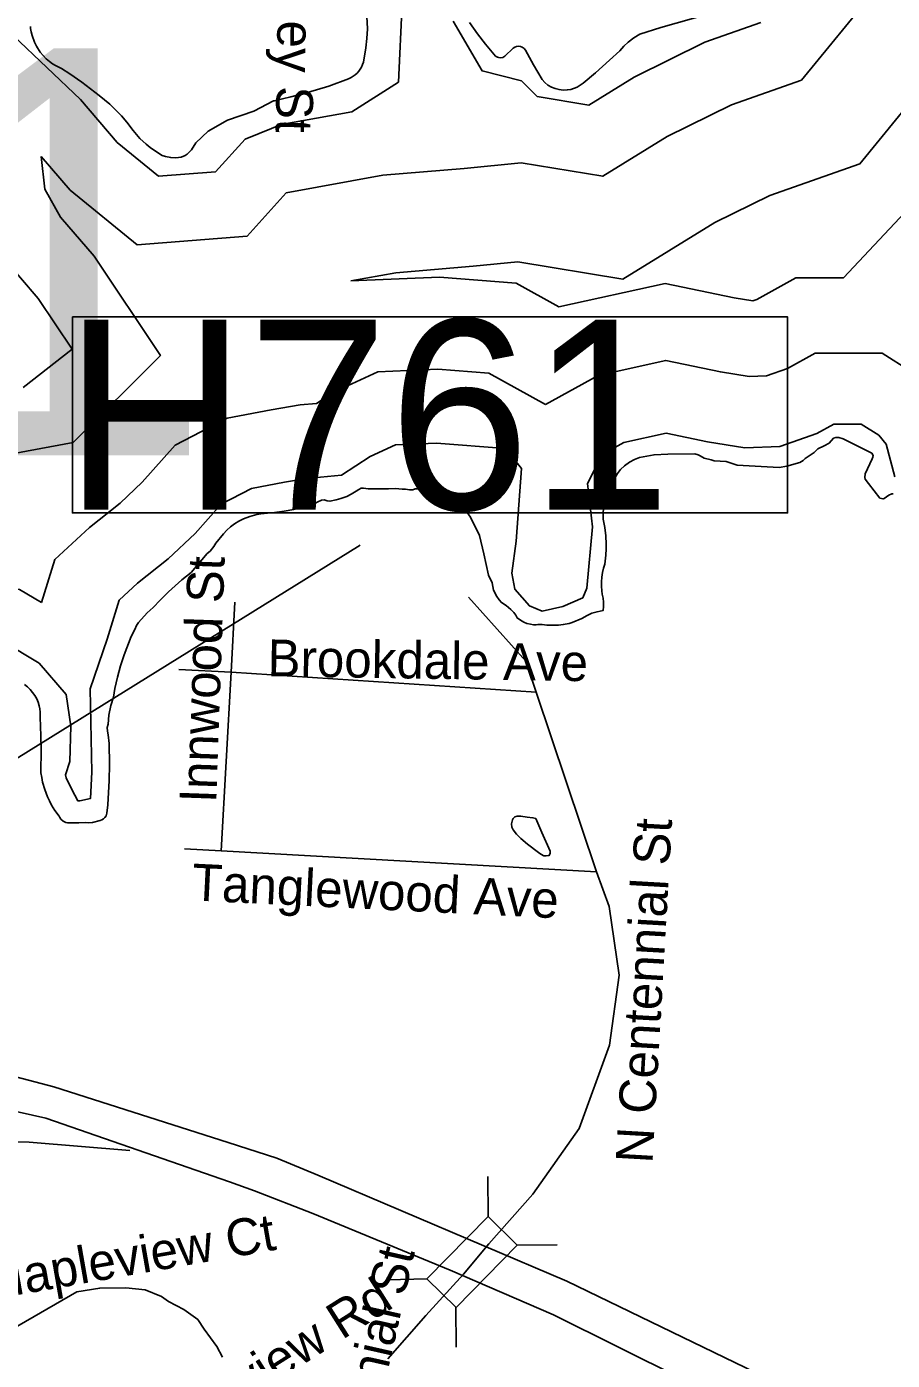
# Model space of a CAD drawing. Extents: x 1662474 to 1856135, y 779280 to 917889.
# Drawn here: x 1702297 to 1704529, y 822946 to 826386 of the extents above; entities that cross this region are included whole.
import ezdxf

# ---------------------------------------------------------------- set-up
doc = ezdxf.new("R2010")
doc.units = 0
for name, color, linetype in [('Exist Hydrographic Lake Shore', 7, 'Continuous'), ('Exist Hydrographic Misc Water Feature', 7, 'Continuous'), ('Exist Road Non-System Structure Non-Sys NCDOT Attributed CELL', 7, 'Continuous'), ('Exist Road Non-System Structure Non-Sys NCDOT Number Label', 7, 'Continuous'), ('Exist Road Non-System Structure Non-Sys Other Number Label', 7, 'Continuous'), ('Exist Road Non-System Type 51', 7, 'Continuous'), ('Exist Road Non-System Type 51 Label', 7, 'Continuous'), ('Exist Road Primary US Divided Attributed', 7, 'Continuous'), ('Old_Level_44', 7, 'Continuous')]:
    doc.layers.add(name, color=color, linetype=linetype)

msp = doc.modelspace()

# ---------------------------------------------------------------- linework, layer by layer
at = {"layer": 'Exist Hydrographic Lake Shore'}
for points in [[(1703439.2, 826397.1), (1703459.2, 826368.2), (1703480.2, 826341.4), (1703506.2, 826310.5), (1703511, 826307.6), (1703514.4, 826306.6), (1703519.6, 826306), (1703524.6, 826307.1), (1703530.1, 826310.5), (1703551.6, 826330.7), (1703555.9, 826333.6), (1703560.5, 826335.4), (1703565.8, 826335.9), (1703570, 826335.4), (1703575, 826333.9), (1703579.8, 826330.4), (1703583.4, 826326), (1703603.9, 826287.6), (1703625.9, 826249.9), (1703633, 826242.2), (1703641.1, 826235.7), (1703650.2, 826230.4), (1703659.8, 826226.5), (1703670, 826224.1), (1703680.2, 826222.8), (1703690.8, 826223.1), (1703700.1, 826224.7), (1703716.5, 826230.7), (1703732.2, 826240.9), (1703763.4, 826267.4), (1703799.9, 826299.8), (1703826.6, 826324.4), (1703836.6, 826335.7), (1703848, 826346.2), (1703862.4, 826357.5), (1703878.1, 826367.2), (1703932.2, 826384.2), (1704050.9, 826417.8)], [(1702306.8, 826386.9), (1702307.2, 826381.9), (1702308.9, 826372.7), (1702311, 826363.8), (1702317, 826346.4), (1702322.2, 826336.2), (1702332.2, 826321), (1702339.6, 826312.1), (1702347.8, 826303.7), (1702356.4, 826296.3), (1702363.8, 826290.8), (1702371.6, 826286.1), (1702387.1, 826278.4), (1702408.6, 826264.6), (1702439.2, 826243.1), (1702483.9, 826208.9), (1702511.2, 826186.4), (1702527, 826171.4), (1702541.4, 826156.2), (1702555, 826140.4)], [(1702555, 826140.4), (1702571.9, 826118.1), (1702580.2, 826107.9), (1702589.1, 826098.2), (1702605.5, 826082.9), (1702615.6, 826074.6), (1702626.5, 826066.7), (1702646.9, 826053.8), (1702655.4, 826051.4), (1702668.8, 826048.8), (1702682.1, 826048.3), (1702695.8, 826049.3), (1702706, 826054.3), (1702710.8, 826057.5), (1702715.6, 826061.9), (1702722, 826069), (1702733.5, 826086.6), (1702764.8, 826116.8), (1702815.1, 826144.9), (1702882.6, 826168.5), (1702933.2, 826195), (1702935.4, 826195), (1702978.6, 826205), (1703021.5, 826216.5), (1703076.2, 826233.3), (1703126.8, 826251.4), (1703133.8, 826254.9), (1703144, 826261.9), (1703149, 826266.7), (1703153.8, 826271.6), (1703160.2, 826282.1), (1703163.1, 826288.4), (1703165.2, 826294.8), (1703171.6, 826332.2), (1703174.2, 826356.2), (1703175.5, 826380.6), (1703174, 826412.6)], [(1704531.4, 825181.6), (1704527.5, 825180.9), (1704520.4, 825177.9), (1704507.8, 825168.8), (1704505.4, 825168), (1704497.2, 825170.4), (1704467.4, 825207.6), (1704459.2, 825219.2), (1704458.1, 825223.6), (1704459.2, 825232.8), (1704477.1, 825271.4), (1704478.6, 825275.9), (1704479.4, 825280.3), (1704475.8, 825286.4), (1704402.5, 825323.4), (1704391, 825326.8), (1704383.6, 825326.8), (1704377.4, 825324.4), (1704366.2, 825311.8), (1704353.1, 825304.8), (1704336.6, 825296.9), (1704327.2, 825288.2), (1704304.4, 825272.4), (1704299.1, 825267.4), (1704291, 825262.2), (1704257.4, 825252.8), (1704237.1, 825249.4), (1704129, 825255.4), (1704101, 825264.8), (1704069.8, 825265.9), (1704061.6, 825269.1), (1704043.5, 825273), (1704034, 825278.8), (1704028.8, 825281.4), (1704019.6, 825284.5), (1703950, 825283.5), (1703914.6, 825282.2), (1703877.4, 825274.6), (1703864, 825269.6), (1703851.4, 825263), (1703838.2, 825253.6), (1703828.2, 825243.6), (1703820.6, 825233.9), (1703814.4, 825223.1), (1703808.9, 825210), (1703804.9, 825196.1), (1703799.1, 825186.6), (1703792.6, 825173.5), (1703788.4, 825161.4), (1703785.2, 825147), (1703783.6, 825134.4), (1703783.4, 825123.9), (1703783.9, 825115.5), (1703785, 825107.1), (1703787.9, 825094.5), (1703790.2, 825072.7), (1703791.2, 825051.2), (1703791.2, 825039.1), (1703790.2, 825022.6), (1703787.4, 825000), (1703784.4, 824989.5), (1703782.1, 824977.9), (1703780.2, 824966.4), (1703779.5, 824954.6), (1703779.5, 824942.6), (1703780, 824930.8), (1703781.2, 824922.1), (1703783.1, 824912.1), (1703784.4, 824902.1), (1703784.4, 824890.3), (1703783.6, 824880.3), (1703767.9, 824877.2), (1703754.5, 824873), (1703742.1, 824867.2), (1703728.2, 824859.3), (1703703.6, 824849.1), (1703695.5, 824846.8), (1703680.8, 824844.1), (1703668.6, 824842.6), (1703653.5, 824842), (1703638.2, 824842.8), (1703626.4, 824844.4), (1703615.9, 824844.4), (1703610.6, 824843.1), (1703603.9, 824843.6), (1703596, 824844.6)], [(1703596, 824844.6), (1703587, 824847), (1703578.6, 824850.4), (1703570.5, 824854.9), (1703562.1, 824861.2), (1703558.5, 824868.2), (1703553.5, 824874.8), (1703548.8, 824879), (1703545.4, 824883.2), (1703533.8, 824892.7), (1703521.1, 824900.8), (1703515.1, 824907.9), (1703509.6, 824916.6), (1703501.2, 824933.1), (1703497.5, 824951.2), (1703487.6, 824971.4), (1703476, 825026.8), (1703464.8, 825073.5), (1703441.4, 825120.8), (1703419.9, 825150.7), (1703402.8, 825165.9), (1703369.5, 825186.1), (1703333, 825191.9), (1703325.9, 825191.6), (1703317.8, 825194.5), (1703298.9, 825193.7), (1703293.1, 825191.9), (1703284.4, 825191.9), (1703274, 825192.9), (1703265.5, 825193.2), (1703247.8, 825194.8), (1703230.4, 825194), (1703177.9, 825194.2), (1703165.2, 825195.8), (1703159.5, 825195.6), (1703153.2, 825192.7), (1703146.6, 825187.7), (1703134, 825180.3), (1703122.5, 825174.3), (1703106.8, 825168.8), (1703095, 825165.6), (1703078.9, 825161.9), (1703071.6, 825162.8), (1703064.2, 825165.4), (1703057.1, 825164.8), (1703046.1, 825160.1), (1703035.4, 825153), (1703010.1, 825146.8), (1702985.8, 825141.2), (1702960.9, 825136.8), (1702936.1, 825133.1), (1702900.8, 825129.4), (1702890.2, 825127.8), (1702872.6, 825123.1), (1702855.9, 825116.6), (1702844, 825110.8), (1702833.2, 825103.7), (1702822.8, 825095.8), (1702813.4, 825087.1), (1702804.4, 825077.7), (1702785.2, 825054.1), (1702779.5, 825045.2), (1702770.5, 825033.6), (1702762.9, 825027.1), (1702721.5, 824978.5), (1702697.6, 824959.1), (1702663.2, 824928.1), (1702641.4, 824906.6), (1702623.2, 824887.7), (1702607.8, 824874.1), (1702585.5, 824849.6), (1702580, 824841.2), (1702575.8, 824831.2), (1702566.9, 824812.9), (1702548.8, 824765.9), (1702539.2, 824737.3), (1702531.1, 824708.4), (1702524.6, 824679.3), (1702520.9, 824656.4), (1702514.4, 824635.4), (1702509.4, 824609.8), (1702507.2, 824587.4), (1702505.1, 824578.8), (1702505.8, 824569.3), (1702507.2, 824559.3), (1702509.6, 824537.1), (1702510.8, 824483.2), (1702509.9, 824441.5), (1702506, 824379), (1702503.6, 824357.2), (1702501.8, 824350.7), (1702498.9, 824346.5), (1702495.5, 824342.8), (1702491.2, 824339.9), (1702486.5, 824338.1), (1702466.6, 824333.6), (1702457.6, 824332.8), (1702448.5, 824333.6), (1702431.4, 824332.6), (1702406.5, 824332.3)], [(1702385.2, 824342.3), (1702382.6, 824346.2), (1702380.8, 824349.6), (1702370, 824364.6), (1702361.6, 824378.2), (1702355.9, 824388.8), (1702350.9, 824399.8), (1702343.8, 824418.4), (1702338.2, 824437.6), (1702335.9, 824449.4), (1702333.8, 824461.2), (1702334.4, 824521.3), (1702333.8, 824557), (1702331.8, 824605.2), (1702332, 824618.1), (1702331.1, 824626.2), (1702329.6, 824634.1), (1702326.8, 824643.6), (1702323, 824652.5), (1702318, 824661.2), (1702312.5, 824669.1), (1702306.2, 824676.4), (1702299.1, 824683.2), (1702291.2, 824689.2)], [(1702406.5, 824332.3), (1702402.6, 824332.6), (1702397.9, 824333.6), (1702391, 824337.1), (1702385.2, 824342.3)]]:
    msp.add_lwpolyline(points, dxfattribs=at)
at = {"layer": 'Exist Hydrographic Misc Water Feature'}
msp.add_lwpolyline([(1703625.6, 824307.2), (1703609.6, 824343.6), (1703602.4, 824345.4), (1703587.7, 824347.4), (1703570.9, 824349.4), (1703561.5, 824349.6), (1703555.8, 824348), (1703551.6, 824344), (1703549.7, 824339.9), (1703547.6, 824330.1), (1703548.1, 824321.1), (1703551.5, 824314.4), (1703560, 824303.6), (1703571.1, 824291.8), (1703588.8, 824277.5), (1703616.7, 824255.7), (1703622.5, 824251.4), (1703630.4, 824247.2), (1703636.4, 824247), (1703644.5, 824248.5), (1703646.8, 824254.2), (1703646.7, 824259.2), (1703625.6, 824307.2)], dxfattribs=at)
msp.add_lwpolyline([(1703625.6, 824307.2), (1703609.6, 824343.6), (1703602.4, 824345.4), (1703587.7, 824347.4), (1703570.9, 824349.4), (1703561.5, 824349.6), (1703555.8, 824348), (1703551.6, 824344), (1703549.7, 824339.9), (1703547.6, 824330.1), (1703548.1, 824321.1), (1703551.5, 824314.4), (1703560, 824303.6), (1703571.1, 824291.8), (1703588.8, 824277.5), (1703616.7, 824255.7), (1703622.5, 824251.4), (1703630.4, 824247.2), (1703636.4, 824247), (1703644.5, 824248.5), (1703646.8, 824254.2), (1703646.7, 824259.2), (1703625.6, 824307.2)], dxfattribs=at)
at = {"layer": 'Exist Road Non-System Structure Non-Sys NCDOT Attributed CELL'}
for p, q in [((1703486, 823419.7), (1703487, 823316.8)), ((1703665, 823244.1), (1703562.1, 823243.1)), ((1703329.1, 823155.9), (1703227.6, 823153.6)), ((1703403.9, 823082.6), (1703404.9, 822979.7))]:
    msp.add_line(p, q, dxfattribs=at)
msp.add_lwpolyline([(1703562.1, 823243.1), (1703404.3, 823082.2), (1703329.1, 823155.9), (1703487, 823316.8)], close=True, dxfattribs=at)
at = {"layer": 'Exist Road Non-System Structure Non-Sys NCDOT Number Label'}
msp.add_line((1701411.8, 823965.3), (1703156.9, 825048.7), dxfattribs=at)
msp.add_lwpolyline([(1702415, 825637.5), (1704258.9, 825637.5), (1704258.9, 825131.9), (1702415, 825131.9)], close=True, dxfattribs=at)
at = {"layer": 'Exist Road Non-System Type 51'}
for p, q in [((1702824.1, 824721), (1702833.8, 824901.9)), ((1702689.1, 824728.4), (1702824.1, 824721)), ((1702798.4, 824259.9), (1702824.1, 824721)), ((1702824.1, 824721), (1703610.4, 824669.6)), ((1703766, 824206.4), (1703610.4, 824669.6)), ((1702704.4, 824265.1), (1702798.4, 824259.9)), ((1702798.4, 824259.9), (1703766, 824206.4)), ((1703423, 823168), (1703488.6, 823246.5))]:
    msp.add_line(p, q, dxfattribs=at)
for points in [[(1703610.4, 824669.6), (1703584.4, 824749.9), (1703436.4, 824914.4)], [(1703488.6, 823246.5), (1703602, 823374.6), (1703721.6, 823543.6), (1703800.1, 823758.9), (1703824.4, 823939.7), (1703799.4, 824116.6), (1703766, 824206.4)], [(1701264.2, 823469.4), (1701519.6, 823477.8), (1701767.9, 823489.2), (1701979.8, 823500.6), (1702105.6, 823505.5), (1702197.9, 823509.5), (1702303.6, 823508.4), (1702563.1, 823487.2)], [(1703228, 822949.7), (1703326.4, 823061.8), (1703423, 823168)], [(1702079.1, 822948.9), (1702144.9, 822960.2), (1702426.9, 823122.6), (1702485.5, 823132.4), (1702553.1, 823133.1), (1702603.1, 823127.9), (1702644.9, 823110.2), (1702663.1, 823097.7), (1702702.5, 823076.9), (1702738.5, 823050.9), (1702755, 823025.8), (1702787.6, 822981.2), (1702802, 822953.9)]]:
    msp.add_lwpolyline(points, dxfattribs=at)
at = {"layer": 'Exist Road Primary US Divided Attributed'}
for points in [[(1705260.4, 822352.9), (1705187.4, 822400), (1705119.1, 822440), (1704867.1, 822576.5), (1704664.6, 822677.7), (1703690.1, 823150.2), (1703048.1, 823423.8), (1702942.1, 823467.2), (1702816.5, 823508.1), (1702367.1, 823651.6), (1702049.5, 823735), (1701806.9, 823785.8), (1701450.7, 823856.2), (1701249.8, 823884.7)], [(1701256.6, 823793.1), (1701413.4, 823767.8), (1701692.2, 823717.2), (1702346.8, 823570.3), (1702820.1, 823406.6), (1702884.4, 823383.2), (1703035, 823324.8), (1703388.9, 823178.6), (1703655.4, 823063.4), (1704652.8, 822567.1), (1704772.9, 822510.6), (1704999, 822390.6), (1705211.3, 822262.7)]]:
    msp.add_lwpolyline(points, dxfattribs=at)
at = {"layer": 'Old_Level_44'}
for points in [[(1706416.7, 828453.3), (1706394.4, 828185.5), (1706206.4, 827887), (1705933.6, 827714.4), (1705493.1, 827597.8), (1705428.1, 827536.3), (1705411.4, 827514), (1705562.9, 827305.8), (1705253, 826872.2), (1704944.5, 826583.1), (1704843.4, 826587.3), (1704694.9, 826337.4), (1704445.7, 826032.9), (1704213.1, 825950.9), (1704071.6, 825880.8), (1703834.3, 825734.9), (1703563.6, 825780), (1703448, 825768.5), (1703249, 825751.6), (1703132.7, 825730.4)], [(1701861.1, 827065.1), (1701815.9, 826970.7), (1701777.6, 826943.2), (1701676.4, 827102.1), (1701582.6, 827175.8), (1701523.2, 827208.2), (1701458.5, 827201), (1701602, 826981.7), (1701687.5, 826826.3), (1701769.3, 826699.2), (1701763.1, 826607.3), (1701828, 826622.5), (1702002.2, 826427.9), (1702044.3, 826243.1), (1702070.3, 826171.7), (1702153.2, 826055.6), (1702169.2, 825911.6), (1702235.9, 825791.6), (1702327.1, 825685.3), (1702414.3, 825554.6), (1702287.7, 825455.1)], [(1702964.1, 826137.9), (1702860.1, 826096.3), (1702783.8, 826011.7), (1702637.3, 826000.4), (1702530.3, 826087.9), (1702435.7, 826198.2), (1702262.2, 826363.7), (1702159.6, 826522.1), (1702183.8, 826618.7), (1702183, 826620.3), (1702107.9, 826632.8), (1702004.2, 826695), (1701861.1, 827065.1)], [(1704486.8, 826483.2), (1704294.5, 826248.3), (1704114.3, 826184.8), (1703948.7, 826102.7), (1703782.4, 826000.4), (1703572.1, 826035.5), (1703424.8, 826020.8), (1703215.6, 826003.1), (1702966.6, 825957.8)], [(1703265.5, 826446.4), (1703255.9, 826243.3), (1703135.3, 826166.7), (1702953.3, 826133.6)], [(1704190, 826397.4), (1704046, 826346.6), (1703863.7, 826256.3), (1703746.5, 826184.2), (1703613.3, 826206.3), (1703572.7, 826246.9), (1703471.4, 826272.2), (1703396.7, 826400.2)], [(1704403.4, 825738.6), (1704640.4, 825991.2), (1704706.4, 826003.2), (1704775.3, 826054.9), (1704827.5, 826211.4), (1705105.4, 826373.4), (1705348.8, 826373.4), (1705403.8, 826349), (1705804.1, 826349), (1705802, 826302.9)], [(1702334.9, 826051.7), (1702344.3, 825967.5), (1702384.5, 825895.1), (1702470.9, 825794.4), (1702641.9, 825538.1), (1702417.3, 825313.7)], [(1702966.6, 825957.8), (1702865.5, 825845.6), (1702581.8, 825823.8), (1702409.7, 825964.5), (1702334.9, 826051.7)], [(1703132.7, 825730.4), (1703361.8, 825740.4), (1703558.9, 825724.7), (1703669.2, 825663.4)], [(1703669.2, 825663.4), (1703943.6, 825723.8), (1704120.9, 825686.9), (1704169.2, 825679.1), (1704179.4, 825682.7), (1704280.1, 825738.6), (1704403.4, 825738.6)], [(1703634.7, 825411.3), (1703770.8, 825486.9), (1703944.7, 825525.2), (1704085.8, 825495.8), (1704159.6, 825484), (1704204.3, 825485.8), (1704258.9, 825504.7), (1704330.4, 825544.4), (1704502.5, 825544.4), (1704576.2, 825497.5)], [(1703002.3, 825410.9), (1703044.7, 825414.6), (1703090.4, 825444.6), (1703202.3, 825496.2), (1703357.6, 825503), (1703488.7, 825492.5), (1703634.7, 825411.3)], [(1702335.3, 824900.7), (1702369.6, 825011.4), (1702459, 825094.6), (1702537.8, 825157.2), (1702595.3, 825211.4), (1702680.3, 825306.9), (1702814.1, 825376.1), (1702927.2, 825397.5), (1703002.3, 825410.9)], [(1703018.9, 825221.1), (1703109.2, 825229), (1703183.2, 825277.6), (1703248, 825307.5), (1703354.1, 825312.1), (1703531.7, 825298.1), (1703572.7, 825246.7), (1703559, 825059.4), (1703547.7, 824976.3), (1703555.8, 824935.6), (1703593.3, 824892.4), (1703626, 824878.4), (1703679.5, 824890.3), (1703731, 824913.2), (1703741.2, 824937.7), (1703756.4, 825096.4), (1703743, 825207.5), (1703780.6, 825282.5), (1703836.4, 825313.5), (1703945.8, 825337.6), (1704052.6, 825315.4), (1704148.7, 825300), (1704238.7, 825303.6), (1704334, 825336.6), (1704377.9, 825360.9), (1704449.1, 825360.9), (1704494.2, 825332.3), (1704513.4, 825308.9), (1704535.3, 825225.1)], [(1702417.3, 825313.7), (1701824.1, 825203.5), (1701675.2, 825171), (1701654, 825175.5), (1701491.7, 825024.7)], [(1702236.2, 824800), (1702329.3, 824744.2), (1702399.2, 824663.1), (1702410.7, 824582.2), (1702408.3, 824490.4), (1702397.6, 824456.5), (1702398.6, 824448.6), (1702413.8, 824418.2), (1702428.9, 824389.3), (1702434.2, 824389.6), (1702461.7, 824395.2), (1702464.8, 824463.2), (1702460.5, 824678.2), (1702504.7, 824806.1), (1702535.9, 824907), (1702582.8, 824950.7), (1702662.1, 825013.7), (1702731.5, 825079.1), (1702798.6, 825154.5), (1702876.6, 825194.8), (1702961.5, 825210.9), (1703018.9, 825221.1)], [(1701491.7, 825024.7), (1701541.9, 824987), (1701610.6, 824881.3), (1701627.7, 824858.5), (1701637.7, 824856.9), (1701721.2, 824833.4), (1701785.6, 824810), (1701793.7, 824805.8), (1701857.9, 824881.9), (1701989, 824944.8), (1702144.5, 824944.8), (1702279, 824934.5), (1702335.3, 824900.7)]]:
    msp.add_lwpolyline(points, dxfattribs=at)

# ---------------------------------------------------------------- texts
at = {"layer": 'Exist Road Non-System Structure Non-Sys NCDOT Number Label'}
msp.add_text('H761', height=490, dxfattribs=at).set_placement((1702392.5, 825140.5))
at = {"layer": 'Exist Road Non-System Structure Non-Sys Other Number Label'}
msp.add_text('J61', height=1049.86, dxfattribs=at).set_placement((1700520.5, 825280.3))
at = {"layer": 'Exist Road Non-System Type 51 Label'}
for s, rotation, p in [('McKinley St', 269.0765, (1702950, 826784)), ('Innwood St', 88.0262, (1702785.9, 824383)), ('Brookdale Ave', 359.1029, (1702917.8, 824710.7)), ('N Centennial St', 86.7365, (1703910.5, 823452.5)), ('Tanglewood Ave', 357.1913, (1702721.6, 824132.5)), ('Mapleview Ct', 9.9346, (1702192.7, 823100.1)), ('N Centennial St', 77.2637, (1703101.8, 822357.8)), ('Oakview Rd', 32.2966, (1702668.5, 822718.5))]:
    msp.add_text(s, height=95, rotation=rotation, dxfattribs=at).set_placement(p)

doc.saveas('drawing.dxf')
